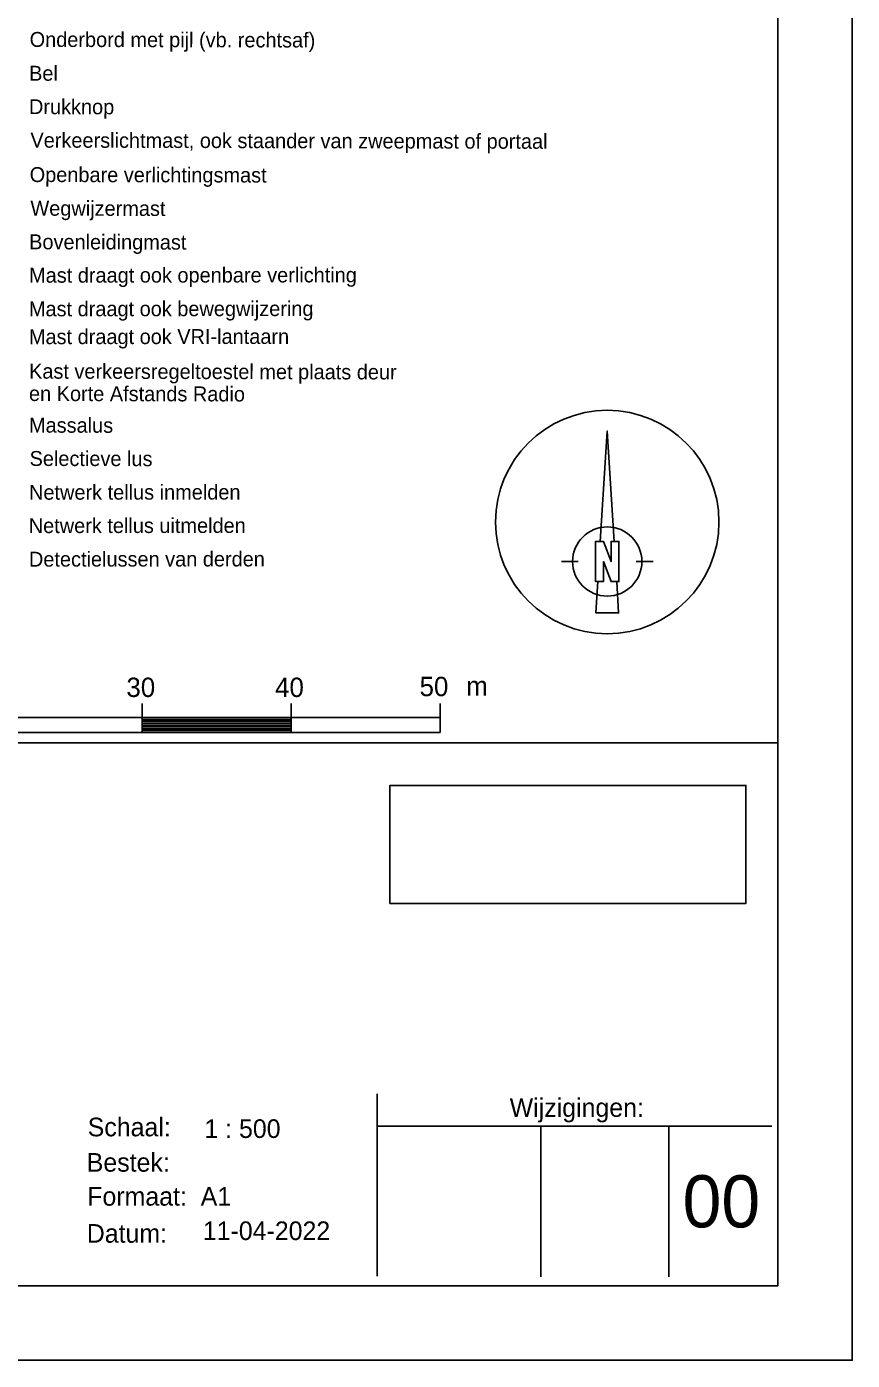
# Model space of a CAD drawing. Extents: x 81065 to 81486, y 452384 to 452681.
# Drawn here: x 81430.3 to 81485.7, y 452383.5 to 452473.1 of the extents above; entities that cross this region are included whole.
import ezdxf

# ---------------------------------------------------------------- set-up
doc = ezdxf.new("R2010")
doc.units = 0
for name, color, linetype in [('Logo', 7, 'Continuous'), ('X-XX-AL-ORIENTATIE-S', 7, 'Continuous'), ('X-XX-AL-TEKENBLAD-S', 7, 'Continuous'), ('X-XX-AL-TEKENBLAD_KADER-G', 7, 'Continuous'), ('X-XX-AL-TEKENBLAD_KADER_AFSNIJMARKERING-G', 7, 'Continuous'), ('X-XX-AL-TEKENBLAD_VERKLARING-T70', 7, 'Continuous'), ('X-XX-AL-TEKENBLAD_VIEWPORT-G', 7, 'Continuous')]:
    doc.layers.add(name, color=color, linetype=linetype)

msp = doc.modelspace()

# ---------------------------------------------------------------- linework, layer by layer
at = {"layer": 'Logo'}
msp.add_lwpolyline([(81454.673, 452414.208), (81478.568, 452414.208), (81478.568, 452422.13), (81454.673, 452422.13)], close=True, dxfattribs=at)
at = {"layer": 'X-XX-AL-ORIENTATIE-S'}
for p, q in [((81467.313, 452437.155), (81466.189, 452437.155)), ((81471.213, 452437.155), (81472.339, 452437.155))]:
    msp.add_line(p, q, dxfattribs=at)
for points in [[(81468.799, 452438.505), (81469.001, 452438.505), (81469.525, 452437.155), (81469.525, 452438.505), (81469.727, 452438.505), (81469.263, 452445.909), (81468.799, 452438.505)], [(81468.475, 452437.549), (81468.475, 452435.805), (81468.631, 452435.805), (81469.001, 452435.805), (81469.001, 452437.155), (81469.525, 452435.805), (81469.897, 452435.805), (81470.051, 452435.805), (81470.051, 452438.505), (81469.727, 452438.505), (81469.525, 452438.505), (81469.525, 452437.155), (81469.001, 452438.505), (81468.799, 452438.505), (81468.475, 452438.505), (81468.475, 452437.549)], [(81469.897, 452435.805), (81469.525, 452435.805), (81469.001, 452437.155), (81469.001, 452435.805), (81468.631, 452435.805), (81468.499, 452433.705), (81470.029, 452433.705), (81469.897, 452435.805)]]:
    msp.add_lwpolyline(points, dxfattribs=at)
msp.add_circle((81469.263, 452437.155), 2.325, dxfattribs=at)
at = {"layer": 'X-XX-AL-TEKENBLAD-S'}
for p, q in [((81438.05, 452425.679), (81438.05, 452427.626)), ((81448.05, 452425.679), (81448.05, 452427.626)), ((81458.05, 452425.679), (81458.05, 452427.626)), ((81408.053, 452426.679), (81458.05, 452426.679)), ((81448.053, 452426.679), (81438.05, 452426.679)), ((81438.05, 452426.553), (81448.05, 452426.553)), ((81438.05, 452426.429), (81448.05, 452426.429)), ((81408.053, 452425.679), (81458.05, 452425.679)), ((81438.05, 452426.303), (81448.05, 452426.303)), ((81438.05, 452426.179), (81448.05, 452426.179)), ((81438.05, 452426.053), (81448.05, 452426.053)), ((81438.05, 452425.929), (81448.05, 452425.929)), ((81438.05, 452425.803), (81448.05, 452425.803)), ((81438.05, 452425.679), (81448.05, 452425.679)), ((81387.021, 452424.987), (81480.708, 452424.987)), ((81480.708, 452388.532), (81480.708, 452424.987)), ((81453.819, 452389.174), (81453.819, 452401.428)), ((81480.306, 452399.253), (81453.877, 452399.253)), ((81464.802, 452389.126), (81464.802, 452399.253)), ((81473.404, 452389.126), (81473.404, 452399.253)), ((81473.404, 452389.126), (81473.404, 452399.253)), ((81387.021, 452388.532), (81480.708, 452388.532))]:
    msp.add_line(p, q, dxfattribs=at)
at = {"layer": 'X-XX-AL-TEKENBLAD_KADER-G'}
msp.add_lwpolyline([(81480.708, 452388.532), (81070.22, 452388.532), (81070.22, 452675.532), (81480.708, 452675.532)], close=True, dxfattribs=at)
at = {"layer": 'X-XX-AL-TEKENBLAD_KADER_AFSNIJMARKERING-G'}
msp.add_lwpolyline([(81485.714, 452680.532), (81065.214, 452680.532), (81065.214, 452383.532), (81485.714, 452383.532)], close=True, dxfattribs=at)
at = {"layer": 'X-XX-AL-TEKENBLAD_VIEWPORT-G'}
msp.add_lwpolyline([(81070.22, 452388.532), (81480.708, 452388.532), (81480.708, 452675.532), (81070.22, 452675.532)], close=True, dxfattribs=at)
msp.add_circle((81469.263, 452439.807), 7.498, dxfattribs=at)

# ---------------------------------------------------------------- texts
at = {"layer": 'X-XX-AL-TEKENBLAD-S'}
for s, height, p in [('30', 1.3, (81436.986, 452428.06)), ('40', 1.3, (81446.966, 452428.06)), ('50', 1.3, (81456.666, 452428.116)), ('m', 1.3, (81459.796, 452428.146)), ('Wijzigingen:', 1.25, (81462.713, 452399.876)), ('Schaal:', 1.25, (81434.39, 452398.569)), ('1 : 500', 1.25, (81442.223, 452398.46)), ('Bestek:', 1.25, (81434.327, 452396.195)), ('Formaat:  A1', 1.25, (81434.358, 452393.915)), ('Datum:', 1.25, (81434.328, 452391.428)), ('11-04-2022', 1.25, (81442.117, 452391.606))]:
    msp.add_text(s, height=height, dxfattribs=at).set_placement(p)
msp.add_text('00', height=3.5, rotation=359.97986, dxfattribs=at).set_placement((81474.32, 452392.456))
at = {"layer": 'X-XX-AL-TEKENBLAD_VERKLARING-T70'}
for s, rotation, p in [('Onderbord met pijl (vb. rechtsaf) ', 359.86856, (81430.49, 452471.704)), ('Bel', 359.86856, (81430.454, 452469.433)), ('Drukknop', 359.86856, (81430.447, 452467.19)), ('Verkeerslichtmast, ook staander van zweepmast of portaal', 359.86856, (81430.543, 452464.94)), ('Openbare verlichtingsmast', 359.86856, (81430.493, 452462.632)), ('Wegwijzermast', 359.86856, (81430.543, 452460.373)), ('Bovenleidingmast', 359.86856, (81430.458, 452458.117)), ('Mast draagt ook openbare verlichting', 0.05984, (81430.454, 452455.872)), ('Mast draagt ook bewegwijzering', 0.05984, (81430.444, 452453.615)), ('Mast draagt ook VRI-lantaarn', 0.05984, (81430.444, 452451.745)), ('Kast verkeersregeltoestel met plaats deur', 359.86856, (81430.451, 452449.432)), ('en Korte Afstands Radio', 359.86856, (81430.448, 452447.932)), ('Massalus', 359.86856, (81430.447, 452445.809)), ('Selectieve lus', 359.86856, (81430.486, 452443.573)), ('Netwerk tellus inmelden', 0.05984, (81430.451, 452441.302)), ('Netwerk tellus uitmelden', 0.05984, (81430.433, 452439.062)), ('Detectielussen van derden', 0.05984, (81430.447, 452436.811))]:
    msp.add_text(s, height=1, rotation=rotation, dxfattribs=at).set_placement(p)

doc.saveas('drawing.dxf')
